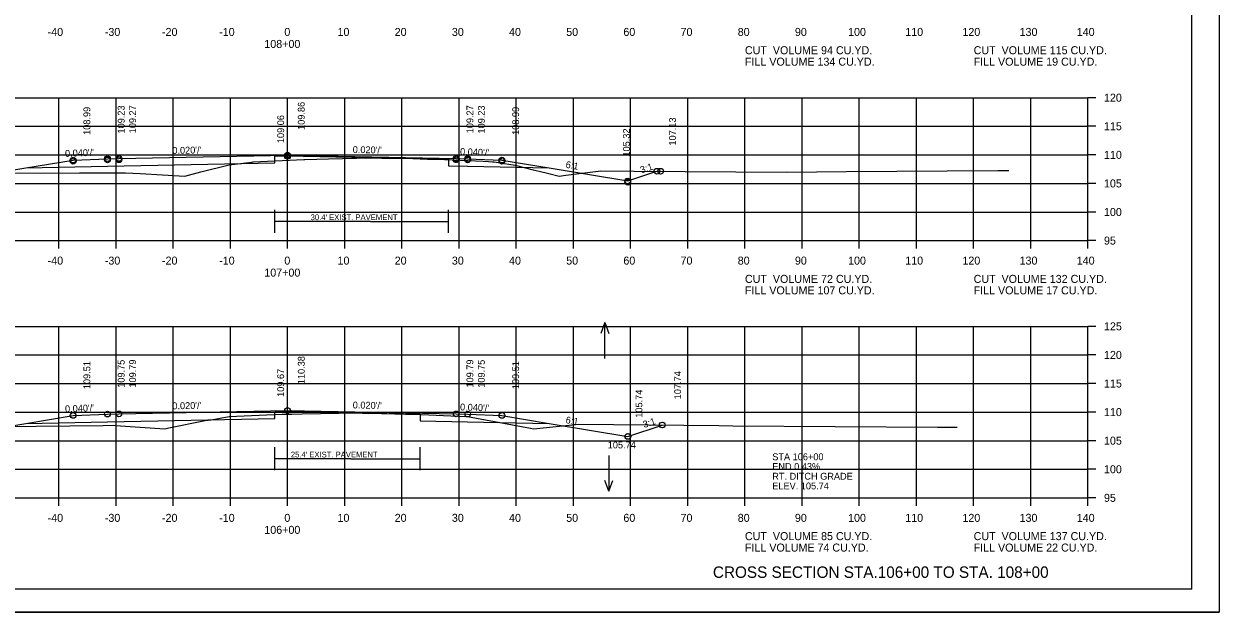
# Model space of a CAD drawing. Extents: x 1175611 to 1176402, y -433344 to -416213.
# Drawn here: x 1175734.9 to 1175943.9, y -432916.9 to -432814 of the extents above; entities that cross this region are included whole.
import ezdxf

# ---------------------------------------------------------------- set-up
doc = ezdxf.new("R2010")
doc.units = 0
for name, color, linetype in [('Default', 7, 'Continuous'), ('R_Alt Surface', 7, 'Continuous'), ('R_Axis', 7, 'Continuous'), ('R_Axis Annot', 7, 'Continuous'), ('R_Border', 7, 'Continuous'), ('R_Draft', 7, 'Continuous'), ('R_Exist Surface', 7, 'Continuous'), ('R_Fin Surface', 7, 'Continuous'), ('R_Grid', 7, 'Continuous'), ('R_No Plot', 7, 'Continuous'), ('R_Water Annot', 7, 'Continuous'), ('R_Xsect Elev', 7, 'Continuous'), ('R_Xsect Slope', 7, 'Continuous')]:
    doc.layers.add(name, color=color, linetype=linetype)

msp = doc.modelspace()

# ---------------------------------------------------------------- linework, layer by layer
at = {"layer": 'R_Alt Surface'}
for points in [[(1175735.2, -432839.15), (1175749.47, -432838.87), (1175778.76, -432838.28), (1175778.76, -432837.12), (1175780.97, -432837.07), (1175809.1, -432837.64), (1175809.1, -432838.8), (1175812.47, -432838.87), (1175826.75, -432839.15)], [(1175735.2, -432883.84), (1175749.47, -432883.55), (1175778.77, -432882.97), (1175778.77, -432881.8), (1175780.97, -432881.76), (1175804.18, -432882.22), (1175804.18, -432883.39), (1175812.47, -432883.55), (1175826.75, -432883.84)]]:
    msp.add_lwpolyline(points, dxfattribs=at)
at = {"layer": 'R_Axis'}
for p, q in [((1175920.97, -432851.87), (1175920.97, -432826.87)), ((1175922.37, -432826.87), (1175920.97, -432826.87)), ((1175922.37, -432831.87), (1175920.97, -432831.87)), ((1175922.37, -432836.87), (1175920.97, -432836.87)), ((1175922.37, -432841.87), (1175920.97, -432841.87)), ((1175922.37, -432846.87), (1175920.97, -432846.87)), ((1175640.97, -432851.87), (1175920.97, -432851.87)), ((1175740.97, -432853.27), (1175740.97, -432851.87)), ((1175750.97, -432853.27), (1175750.97, -432851.87)), ((1175760.97, -432853.27), (1175760.97, -432851.87)), ((1175770.97, -432853.27), (1175770.97, -432851.87)), ((1175780.97, -432853.27), (1175780.97, -432851.87)), ((1175790.97, -432853.27), (1175790.97, -432851.87)), ((1175800.97, -432853.27), (1175800.97, -432851.87)), ((1175810.97, -432853.27), (1175810.97, -432851.87)), ((1175820.97, -432853.27), (1175820.97, -432851.87)), ((1175830.97, -432853.27), (1175830.97, -432851.87)), ((1175840.97, -432853.27), (1175840.97, -432851.87)), ((1175850.97, -432853.27), (1175850.97, -432851.87)), ((1175860.97, -432853.27), (1175860.97, -432851.87)), ((1175870.97, -432853.27), (1175870.97, -432851.87)), ((1175880.97, -432853.27), (1175880.97, -432851.87)), ((1175890.97, -432853.27), (1175890.97, -432851.87)), ((1175900.97, -432853.27), (1175900.97, -432851.87)), ((1175910.97, -432853.27), (1175910.97, -432851.87)), ((1175920.97, -432853.27), (1175920.97, -432851.87)), ((1175922.37, -432851.87), (1175920.97, -432851.87)), ((1175920.97, -432896.87), (1175920.97, -432866.87)), ((1175922.37, -432866.87), (1175920.97, -432866.87)), ((1175922.37, -432871.87), (1175920.97, -432871.87)), ((1175922.37, -432876.87), (1175920.97, -432876.87)), ((1175922.37, -432881.87), (1175920.97, -432881.87)), ((1175922.37, -432886.87), (1175920.97, -432886.87)), ((1175922.37, -432891.87), (1175920.97, -432891.87)), ((1175640.97, -432896.87), (1175920.97, -432896.87)), ((1175740.97, -432898.27), (1175740.97, -432896.87)), ((1175750.97, -432898.27), (1175750.97, -432896.87)), ((1175760.97, -432898.27), (1175760.97, -432896.87)), ((1175770.97, -432898.27), (1175770.97, -432896.87)), ((1175780.97, -432898.27), (1175780.97, -432896.87)), ((1175790.97, -432898.27), (1175790.97, -432896.87)), ((1175800.97, -432898.27), (1175800.97, -432896.87)), ((1175810.97, -432898.27), (1175810.97, -432896.87)), ((1175820.97, -432898.27), (1175820.97, -432896.87)), ((1175830.97, -432898.27), (1175830.97, -432896.87)), ((1175840.97, -432898.27), (1175840.97, -432896.87)), ((1175850.97, -432898.27), (1175850.97, -432896.87)), ((1175860.97, -432898.27), (1175860.97, -432896.87)), ((1175870.97, -432898.27), (1175870.97, -432896.87)), ((1175880.97, -432898.27), (1175880.97, -432896.87)), ((1175890.97, -432898.27), (1175890.97, -432896.87)), ((1175900.97, -432898.27), (1175900.97, -432896.87)), ((1175910.97, -432898.27), (1175910.97, -432896.87)), ((1175920.97, -432898.27), (1175920.97, -432896.87)), ((1175922.37, -432896.87), (1175920.97, -432896.87))]:
    msp.add_line(p, q, dxfattribs=at)
at = {"layer": 'R_Border'}
for q in [(1175939.15, -432707.41), (1175622.97, -432912.87)]:
    msp.add_line((1175939.15, -432912.87), q, dxfattribs=at)
at = {"layer": 'R_Draft'}
for p, q in [((1175795.5, -432848.51), (1175778.76, -432848.51)), ((1175795.5, -432848.51), (1175809.1, -432848.51)), ((1175792.04, -432890.02), (1175778.77, -432890.02)), ((1175792.04, -432890.02), (1175804.18, -432890.02))]:
    msp.add_line(p, q, dxfattribs=at)
for points in [[(1175778.76, -432850.51), (1175778.76, -432846.51)], [(1175809.1, -432850.51), (1175809.1, -432846.51)], [(1175778.77, -432892.02), (1175778.77, -432888.02)], [(1175804.18, -432892.02), (1175804.18, -432888.02)]]:
    msp.add_lwpolyline(points, dxfattribs=at)
at = {"layer": 'R_Exist Surface'}
for points in [[(1175720.25, -432840.12), (1175744.6, -432840.03), (1175752.65, -432840.02), (1175755.22, -432840.15), (1175762.98, -432840.6), (1175765.81, -432839.86), (1175770.76, -432838.61), (1175774.67, -432838.14), (1175774.76, -432838.14), (1175774.78, -432838.13), (1175774.85, -432838.13), (1175774.94, -432838.12), (1175783.8, -432837.67), (1175783.82, -432837.67), (1175783.98, -432837.66), (1175786.11, -432837.63), (1175788.14, -432837.59), (1175793.04, -432837.46), (1175795.48, -432837.4), (1175795.5, -432837.4), (1175795.64, -432837.4), (1175796.82, -432837.41), (1175797.46, -432837.43), (1175798.78, -432837.46), (1175799.75, -432837.48), (1175800.58, -432837.48), (1175801.07, -432837.48), (1175802.89, -432837.53), (1175805.47, -432837.61), (1175806.14, -432837.6), (1175807.07, -432837.6), (1175815.18, -432838), (1175816.14, -432838.05), (1175816.79, -432838.08), (1175817.1, -432838.12), (1175817.81, -432838.23), (1175820.8, -432838.7), (1175823.91, -432839.48), (1175824.97, -432839.72), (1175826.65, -432840.14), (1175828.48, -432840.58), (1175829.64, -432840.42), (1175835.78, -432839.66), (1175841.6, -432839.71), (1175868.31, -432839.9), (1175878.7, -432839.77), (1175905.18, -432839.6), (1175905.81, -432839.6), (1175907.15, -432839.6)], [(1175719.38, -432884.52), (1175748.73, -432884.2), (1175750.48, -432884.18), (1175750.89, -432884.21), (1175759.49, -432884.8), (1175760.18, -432884.65), (1175766.58, -432883.37), (1175767.63, -432883.2), (1175770.77, -432882.63), (1175777.27, -432882.33), (1175780.04, -432882.22), (1175781.71, -432882.21), (1175783.52, -432882.18), (1175786.74, -432882.1), (1175789.92, -432882.03), (1175790.87, -432882.02), (1175791.62, -432882.02), (1175792.37, -432882.01), (1175793.03, -432882), (1175794.1, -432882.05), (1175795.12, -432882.09), (1175796.32, -432882.08), (1175797.41, -432882.09), (1175799.73, -432882.16), (1175801.61, -432882.21), (1175802.52, -432882.21), (1175803.04, -432882.21), (1175812.18, -432882.63), (1175812.32, -432882.64), (1175812.39, -432882.64), (1175812.42, -432882.65), (1175823.49, -432884.7), (1175823.96, -432884.8), (1175831.35, -432884.03), (1175831.86, -432883.98), (1175856.4, -432884.23), (1175858.86, -432884.25), (1175894.66, -432884.52), (1175896.1, -432884.53), (1175896.18, -432884.53), (1175898.08, -432884.53)]]:
    msp.add_lwpolyline(points, dxfattribs=at)
at = {"layer": 'R_Fin Surface'}
for points in [[(1175717.46, -432840.1), (1175721.47, -432841.44), (1175735.2, -432839.15), (1175743.47, -432837.78), (1175749.47, -432837.54), (1175751.47, -432837.5), (1175780.97, -432836.91), (1175810.47, -432837.5), (1175812.47, -432837.54), (1175818.47, -432837.78), (1175826.75, -432839.15), (1175840.47, -432841.44), (1175845.58, -432839.74)], [(1175717.46, -432840.1), (1175721.47, -432841.44), (1175735.2, -432839.15), (1175743.47, -432837.78), (1175749.47, -432837.54), (1175751.47, -432837.5), (1175780.97, -432836.91), (1175810.47, -432837.5), (1175812.47, -432837.54), (1175818.47, -432837.78), (1175826.75, -432839.15), (1175840.47, -432841.44), (1175845.58, -432839.74)], [(1175716.59, -432884.5), (1175721.47, -432886.13), (1175735.2, -432883.84), (1175743.47, -432882.46), (1175749.47, -432882.22), (1175751.47, -432882.18), (1175780.97, -432881.59), (1175810.47, -432882.18), (1175812.47, -432882.22), (1175818.47, -432882.46), (1175826.75, -432883.84), (1175840.47, -432886.13), (1175840.5, -432886.13), (1175846.51, -432884.13)], [(1175716.59, -432884.5), (1175721.47, -432886.13), (1175735.2, -432883.84), (1175743.47, -432882.46), (1175749.47, -432882.22), (1175751.47, -432882.18), (1175780.97, -432881.59), (1175810.47, -432882.18), (1175812.47, -432882.22), (1175818.47, -432882.46), (1175826.75, -432883.84), (1175840.47, -432886.13), (1175840.5, -432886.13), (1175846.51, -432884.13)]]:
    msp.add_lwpolyline(points, dxfattribs=at)
at = {"layer": 'R_Grid'}
for p, q in [((1175640.97, -432826.87), (1175920.97, -432826.87)), ((1175740.97, -432851.87), (1175740.97, -432826.87)), ((1175750.97, -432851.87), (1175750.97, -432826.87)), ((1175760.97, -432851.87), (1175760.97, -432826.87)), ((1175770.97, -432851.87), (1175770.97, -432826.87)), ((1175780.97, -432851.87), (1175780.97, -432826.87)), ((1175790.97, -432851.87), (1175790.97, -432826.87)), ((1175800.97, -432851.87), (1175800.97, -432826.87)), ((1175810.97, -432851.87), (1175810.97, -432826.87)), ((1175820.97, -432851.87), (1175820.97, -432826.87)), ((1175830.97, -432851.87), (1175830.97, -432826.87)), ((1175840.97, -432851.87), (1175840.97, -432826.87)), ((1175850.97, -432851.87), (1175850.97, -432826.87)), ((1175860.97, -432851.87), (1175860.97, -432826.87)), ((1175870.97, -432851.87), (1175870.97, -432826.87)), ((1175880.97, -432851.87), (1175880.97, -432826.87)), ((1175890.97, -432851.87), (1175890.97, -432826.87)), ((1175900.97, -432851.87), (1175900.97, -432826.87)), ((1175910.97, -432851.87), (1175910.97, -432826.87)), ((1175920.97, -432851.87), (1175920.97, -432826.87)), ((1175640.97, -432831.87), (1175920.97, -432831.87)), ((1175640.97, -432836.87), (1175920.97, -432836.87)), ((1175640.97, -432841.87), (1175920.97, -432841.87)), ((1175640.97, -432846.87), (1175920.97, -432846.87)), ((1175640.97, -432851.87), (1175920.97, -432851.87)), ((1175640.97, -432866.87), (1175920.97, -432866.87)), ((1175740.97, -432896.87), (1175740.97, -432866.87)), ((1175750.97, -432896.87), (1175750.97, -432866.87)), ((1175760.97, -432896.87), (1175760.97, -432866.87)), ((1175770.97, -432896.87), (1175770.97, -432866.87)), ((1175780.97, -432896.87), (1175780.97, -432866.87)), ((1175790.97, -432896.87), (1175790.97, -432866.87)), ((1175800.97, -432896.87), (1175800.97, -432866.87)), ((1175810.97, -432896.87), (1175810.97, -432866.87)), ((1175820.97, -432896.87), (1175820.97, -432866.87)), ((1175830.97, -432896.87), (1175830.97, -432866.87)), ((1175840.97, -432896.87), (1175840.97, -432866.87)), ((1175850.97, -432896.87), (1175850.97, -432866.87)), ((1175860.97, -432896.87), (1175860.97, -432866.87)), ((1175870.97, -432896.87), (1175870.97, -432866.87)), ((1175880.97, -432896.87), (1175880.97, -432866.87)), ((1175890.97, -432896.87), (1175890.97, -432866.87)), ((1175900.97, -432896.87), (1175900.97, -432866.87)), ((1175910.97, -432896.87), (1175910.97, -432866.87)), ((1175920.97, -432896.87), (1175920.97, -432866.87)), ((1175640.97, -432871.87), (1175920.97, -432871.87)), ((1175640.97, -432876.87), (1175920.97, -432876.87)), ((1175640.97, -432881.87), (1175920.97, -432881.87)), ((1175640.97, -432886.87), (1175920.97, -432886.87)), ((1175640.97, -432891.87), (1175920.97, -432891.87)), ((1175640.97, -432896.87), (1175920.97, -432896.87))]:
    msp.add_line(p, q, dxfattribs=at)
at = {"layer": 'R_No Plot'}
for p, q in [((1175783.8, -432837.4), (1175783.8, -432837.4)), ((1175610.57, -432916.85), (1175943.91, -432916.85))]:
    msp.add_line(p, q, dxfattribs=at)
msp.add_lwpolyline([(1175610.57, -432703.52), (1175943.91, -432703.52), (1175943.91, -432916.86), (1175610.57, -432916.86)], close=True, dxfattribs=at)
for centre in [(1175780.97, -432836.91), (1175780.97, -432837.13), (1175743.47, -432837.78), (1175743.47, -432838), (1175749.47, -432837.54), (1175749.47, -432837.76), (1175751.47, -432837.5), (1175751.47, -432837.72), (1175810.47, -432837.5), (1175810.47, -432837.72), (1175812.47, -432837.54), (1175812.47, -432837.76), (1175818.47, -432837.78), (1175818.47, -432838), (1175840.47, -432841.44), (1175845.58, -432839.74), (1175845.58, -432839.74), (1175846.23, -432839.74), (1175840.47, -432841.66), (1175743.47, -432882.46), (1175743.47, -432882.46), (1175749.47, -432882.22), (1175749.47, -432882.22), (1175751.47, -432882.18), (1175751.47, -432882.18), (1175780.97, -432881.59), (1175780.97, -432881.59), (1175810.47, -432882.18), (1175810.47, -432882.18), (1175812.47, -432882.22), (1175812.47, -432882.22), (1175818.47, -432882.46), (1175818.47, -432882.46), (1175846.5, -432884.13), (1175846.51, -432884.13), (1175846.51, -432884.13), (1175840.47, -432886.13), (1175840.47, -432886.13), (1175840.48, -432886.13), (1175840.5, -432886.13), (1175840.5, -432886.13)]:
    msp.add_circle(centre, 0.5, dxfattribs=at)
at = {"layer": 'R_Water Annot'}
for p, q in [((1175836.45, -432866.2), (1175835.75, -432868.12)), ((1175836.45, -432872.48), (1175836.45, -432866.2)), ((1175836.45, -432866.2), (1175837.15, -432868.12)), ((1175837.18, -432889.45), (1175837.18, -432895.73)), ((1175837.18, -432895.73), (1175836.48, -432893.81)), ((1175837.18, -432895.73), (1175837.88, -432893.81))]:
    msp.add_line(p, q, dxfattribs=at)

# ---------------------------------------------------------------- texts
at = {"layer": 'Default'}
for s, p in [('CUT  VOLUME 94 CU.YD.', (1175860.97, -432819.27)), ('CUT  VOLUME 115 CU.YD.', (1175900.97, -432819.27)), ('FILL VOLUME 134 CU.YD.', (1175860.97, -432821.27)), ('FILL VOLUME 19 CU.YD.', (1175900.97, -432821.27)), ('CUT  VOLUME 72 CU.YD.', (1175860.97, -432859.27)), ('CUT  VOLUME 132 CU.YD.', (1175900.97, -432859.27)), ('FILL VOLUME 107 CU.YD.', (1175860.97, -432861.27)), ('FILL VOLUME 17 CU.YD.', (1175900.97, -432861.27)), ('CUT  VOLUME 85 CU.YD.', (1175860.97, -432904.27)), ('CUT  VOLUME 137 CU.YD.', (1175900.97, -432904.27)), ('FILL VOLUME 74 CU.YD.', (1175860.97, -432906.27)), ('FILL VOLUME 22 CU.YD.', (1175900.97, -432906.27))]:
    msp.add_text(s, height=1.4, dxfattribs=at).set_placement(p)
at = {"layer": 'R_Axis Annot'}
for s, p in [('-40', (1175739.01, -432816.07)), ('-30', (1175749.01, -432816.07)), ('-20', (1175759.01, -432816.07)), ('-10', (1175769.01, -432816.07)), ('0', (1175780.41, -432816.07)), ('10', (1175789.71, -432816.07)), ('20', (1175799.71, -432816.07)), ('30', (1175809.71, -432816.07)), ('40', (1175819.71, -432816.07)), ('50', (1175829.71, -432816.07)), ('60', (1175839.71, -432816.07)), ('70', (1175849.71, -432816.07)), ('80', (1175859.71, -432816.07)), ('90', (1175869.71, -432816.07)), ('100', (1175879.01, -432816.07)), ('110', (1175889.01, -432816.07)), ('120', (1175899.01, -432816.07)), ('130', (1175909.01, -432816.07)), ('140', (1175919.01, -432816.07)), ('108+00', (1175776.91, -432818.17)), ('120', (1175923.77, -432827.57)), ('115', (1175923.77, -432832.57)), ('110', (1175923.77, -432837.57)), ('105', (1175923.77, -432842.57)), ('100', (1175923.77, -432847.57)), ('95', (1175923.77, -432852.57)), ('-40', (1175739.01, -432856.07)), ('-30', (1175749.01, -432856.07)), ('-20', (1175759.01, -432856.07)), ('-10', (1175769.01, -432856.07)), ('0', (1175780.41, -432856.07)), ('10', (1175789.71, -432856.07)), ('20', (1175799.71, -432856.07)), ('30', (1175809.71, -432856.07)), ('40', (1175819.71, -432856.07)), ('50', (1175829.71, -432856.07)), ('60', (1175839.71, -432856.07)), ('70', (1175849.71, -432856.07)), ('80', (1175859.71, -432856.07)), ('90', (1175869.71, -432856.07)), ('100', (1175879.01, -432856.07)), ('110', (1175889.01, -432856.07)), ('120', (1175899.01, -432856.07)), ('130', (1175909.01, -432856.07)), ('140', (1175919.01, -432856.07)), ('107+00', (1175776.91, -432858.17)), ('125', (1175923.77, -432867.57)), ('120', (1175923.77, -432872.57)), ('115', (1175923.77, -432877.57)), ('110', (1175923.77, -432882.57)), ('105', (1175923.77, -432887.57)), ('100', (1175923.77, -432892.57)), ('95', (1175923.77, -432897.57)), ('-40', (1175739.01, -432901.07)), ('-30', (1175749.01, -432901.07)), ('-20', (1175759.01, -432901.07)), ('-10', (1175769.01, -432901.07)), ('0', (1175780.41, -432901.07)), ('10', (1175789.71, -432901.07)), ('20', (1175799.71, -432901.07)), ('30', (1175809.71, -432901.07)), ('40', (1175819.71, -432901.07)), ('50', (1175829.71, -432901.07)), ('60', (1175839.71, -432901.07)), ('70', (1175849.71, -432901.07)), ('80', (1175859.71, -432901.07)), ('90', (1175869.71, -432901.07)), ('100', (1175879.01, -432901.07)), ('110', (1175889.01, -432901.07)), ('120', (1175899.01, -432901.07)), ('130', (1175909.01, -432901.07)), ('140', (1175919.01, -432901.07)), ('106+00', (1175776.91, -432903.17))]:
    msp.add_text(s, height=1.4, dxfattribs=at).set_placement(p)
at = {"layer": 'R_Draft'}
for s, height, p in [("30.4' EXIST. PAVEMENT", 1, (1175785.01, -432848.29)), ("25.4' EXIST. PAVEMENT", 1, (1175781.54, -432889.8)), ('CROSS SECTION STA.106+00 TO STA. 108+00', 2, (1175855.37, -432910.87))]:
    msp.add_text(s, height=height, dxfattribs=at).set_placement(p)
at = {"layer": 'R_Water Annot'}
for s, p in [('STA 106+00', (1175865.75, -432890.29)), ('END 0.43%', (1175865.75, -432891.99)), ('RT. DITCH GRADE', (1175865.75, -432893.69)), ('ELEV. 105.74', (1175865.75, -432895.39))]:
    msp.add_text(s, height=1.2, dxfattribs=at).set_placement(p)
at = {"layer": 'R_Xsect Elev'}
for s, p in [('109.23', (1175752.47, -432833.14)), ('109.27', (1175754.47, -432833.1)), ('109.86', (1175783.97, -432832.51)), ('109.27', (1175813.47, -432833.1)), ('109.23', (1175815.47, -432833.14)), ('108.99', (1175746.47, -432833.38)), ('109.06', (1175780.37, -432834.82)), ('108.99', (1175821.47, -432833.38)), ('107.13', (1175848.9, -432835.24)), ('105.32', (1175840.84, -432837.17)), ('110.38', (1175783.97, -432876.99)), ('109.51', (1175746.47, -432877.86)), ('109.75', (1175752.47, -432877.62)), ('109.79', (1175754.47, -432877.58)), ('109.67', (1175780.37, -432879.21)), ('109.79', (1175813.47, -432877.58)), ('109.75', (1175815.47, -432877.62)), ('109.51', (1175821.47, -432877.86)), ('107.74', (1175849.8, -432879.63)), ('105.74', (1175843.03, -432882.85))]:
    msp.add_text(s, height=1.2, rotation=90, dxfattribs=at).set_placement(p)
msp.add_text('105.74', height=1.2, dxfattribs=at).set_placement((1175836.97, -432888.22))
at = {"layer": 'R_Xsect Slope'}
for s, rotation, p in [("0.040'/'", 2.2906, (1175742.07, -432837.23)), ("0.020'/'", 1.1458, (1175760.83, -432836.71)), ("0.020'/'", 358.8542, (1175792.36, -432836.53)), ("0.040'/'", 357.7094, (1175811.12, -432836.88)), ('6:1', 350.5377, (1175829.55, -432839.12)), ('3:1', 18.4349, (1175842.87, -432840.12)), ("0.040'/'", 2.2906, (1175742.07, -432881.91)), ("0.020'/'", 1.1458, (1175760.83, -432881.39)), ("0.020'/'", 358.8542, (1175792.36, -432881.22)), ("0.040'/'", 357.7094, (1175811.12, -432881.56)), ('6:1', 350.5377, (1175829.55, -432883.8)), ('3:1', 18.4349, (1175843.35, -432884.66))]:
    msp.add_text(s, height=1.2, rotation=rotation, dxfattribs=at).set_placement(p)

doc.saveas('drawing.dxf')
